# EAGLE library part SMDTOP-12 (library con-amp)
AMP connector
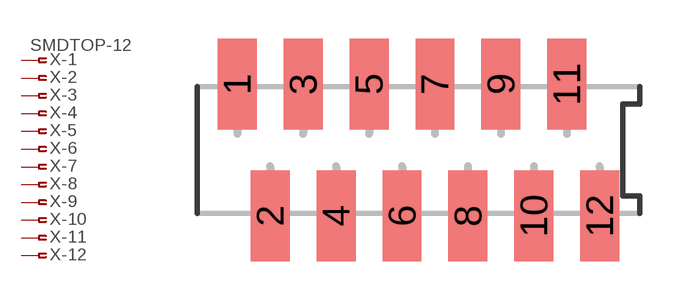
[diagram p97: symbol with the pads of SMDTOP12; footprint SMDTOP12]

Designator prefix X; gates -1=PIN-FV -2=PIN-F -3=PIN-F -4=PIN-F -5=PIN-F -6=PIN-F -7=PIN-F -8=PIN-F -9=PIN-F -10=PIN-F -11=PIN-F -12=PIN-F

## SMDTOP-12 (OC_FARNELL: unknown; OC_NEWARK: unknown)  [SMDTOP12]
1  -1:1  pas
2  -2:1  pas
3  -3:1  pas
4  -4:1  pas
5  -5:1  pas
6  -6:1  pas
7  -7:1  pas
8  -8:1  pas
9  -9:1  pas
10  -10:1  pas
11  -11:1  pas
12  -12:1  pas

## Footprint SMDTOP12 (pad centres in mm)
AMP connector
smd 1.5 x 3.5: 1 -6.985,2.54; 2 -5.715,-2.54; 3 -4.445,2.54; 4 -3.175,-2.54; 5 -1.905,2.54; 6 -0.635,-2.54; 7 0.635,2.54; 8 1.905,-2.54; 9 3.175,2.54; 10 4.445,-2.54; 11 5.715,2.54; 12 6.985,-2.54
